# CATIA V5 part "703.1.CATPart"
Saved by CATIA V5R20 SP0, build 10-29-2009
Part number: 703.1
Revision: QUALSIASI
Definition: SCONOSCIUTO
Nomenclature: 703.1
Source: Unknown
Bounding box of the stored display mesh (mm): x -50 to 50, y -50 to 50, z 0 to 25
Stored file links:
  C:\Users\Utente\Desktop\IO LAVORO\3D X SITO CF\X 3D SITO CF 27-09-2020\703\703.1.CATPart
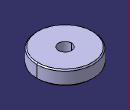
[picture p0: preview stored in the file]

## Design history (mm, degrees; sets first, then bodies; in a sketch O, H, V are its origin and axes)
Body1 "NONE" (main body)
  Solid1: solid without history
